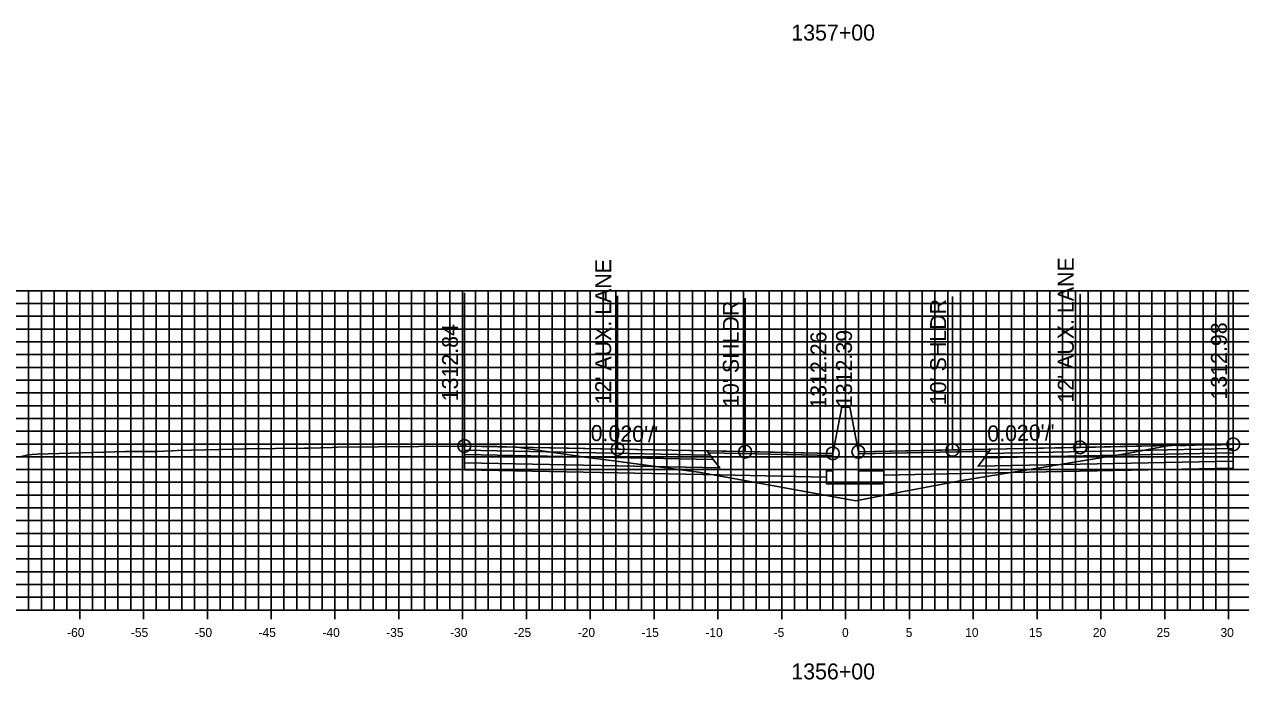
# Model space of a CAD drawing. Extents: x 674939 to 678919, y 750652 to 765176.
# Drawn here: x 678674.2 to 678769.5, y 753742.1 to 753793.4 of the extents above; entities that cross this region are included whole.
import ezdxf

# ---------------------------------------------------------------- set-up
doc = ezdxf.new("R2010")
doc.units = 0
for name, color, linetype in [('Level 10', 7, 'Continuous'), ('Level 17', 7, 'Continuous'), ('Level 18', 7, 'Continuous'), ('Level 19', 7, 'Continuous'), ('Level 20', 7, 'Continuous'), ('Level 22', 7, 'Continuous'), ('Level 23', 7, 'Continuous'), ('Level 4', 7, 'Continuous'), ('Level 8', 7, 'Continuous'), ('Level 9', 7, 'Continuous')]:
    doc.layers.add(name, color=color, linetype=linetype)

msp = doc.modelspace()

# ---------------------------------------------------------------- linework, layer by layer
at = {"layer": 'Level 10'}
msp.add_lwpolyline([(678673.696, 753759.531), (678674.327, 753759.663), (678674.356, 753759.666), (678674.804, 753759.734), (678675.19, 753759.744), (678682.129, 753759.956), (678682.267, 753759.958), (678684.516, 753759.968), (678684.604, 753759.969), (678684.634, 753759.971), (678685.137, 753759.996), (678685.157, 753759.997), (678685.779, 753760.029), (678686.181, 753760.038), (678691.617, 753760.166), (678696.114, 753760.216), (678696.405, 753760.219), (678696.417, 753760.218), (678696.455, 753760.223), (678698.329, 753760.287), (678698.696, 753760.292), (678708.309, 753760.389), (678708.576, 753760.391), (678708.668, 753760.393), (678708.677, 753760.393), (678708.805, 753760.394), (678708.869, 753760.39), (678710.367, 753760.35), (678710.468, 753760.351), (678711.218, 753760.352), (678712.717, 753760.298), (678712.806, 753760.296), (678714.737, 753760.016), (678717.61, 753759.598), (678718.097, 753759.528), (678720.168, 753759.252), (678727.002, 753758.341), (678730.892, 753757.635), (678739.341, 753756.11), (678742.378, 753756.695), (678747.651, 753757.691), (678752.616, 753758.5), (678760.729, 753759.828), (678763.193, 753760.303), (678764.325, 753760.508), (678764.396, 753760.507), (678764.486, 753760.487), (678764.766, 753760.427), (678764.886, 753760.425), (678765.185, 753760.445), (678766.586, 753760.473), (678767.244, 753760.473), (678767.945, 753760.473), (678768.698, 753760.51), (678768.877, 753760.53), (678768.906, 753760.529), (678769.135, 753760.54), (678769.823, 753760.534)], dxfattribs=at)
at = {"layer": 'Level 17'}
for points in [[(678738.203, 753763.315), (678737.533, 753759.815)], [(678738.863, 753763.442), (678738.863, 753763.442), (678738.203, 753763.442), (678738.203, 753763.315)], [(678738.863, 753763.442), (678739.533, 753759.942)], [(678737.533, 753759.815), (678737.533, 753758.44), (678737.033, 753758.44), (678737.033, 753757.44), (678741.533, 753757.44), (678741.533, 753758.44), (678739.533, 753758.44), (678739.533, 753759.942)]]:
    msp.add_lwpolyline(points, dxfattribs=at)
at = {"layer": 'Level 18'}
for points in [[(678737.533, 753759.815), (678730.668, 753759.953), (678720.668, 753760.153), (678708.668, 753760.393)], [(678768.906, 753760.529), (678756.906, 753760.289), (678746.906, 753760.089), (678739.533, 753759.942)]]:
    msp.add_lwpolyline(points, dxfattribs=at)
for points in [[(678708.668, 753760.393), (678708.668, 753760.063), (678727.918, 753759.678), (678727.668, 753760.013)], [(678727.668, 753760.013), (678737.533, 753759.815), (678737.537, 753759.658), (678727.787, 753759.853)], [(678749.787, 753759.99), (678739.533, 753759.785), (678739.533, 753759.942), (678749.906, 753760.149)], [(678768.906, 753760.529), (678768.906, 753760.199), (678749.656, 753759.814), (678749.906, 753760.149)]]:
    msp.add_lwpolyline(points, close=True, dxfattribs=at)
at = {"layer": 'Level 19'}
for points in [[(678708.668, 753760.063), (678708.668, 753759.733), (678728.168, 753759.343), (678727.918, 753759.678)], [(678768.906, 753760.199), (678768.906, 753759.869), (678749.406, 753759.479), (678749.656, 753759.814)], [(678708.668, 753759.733), (678708.668, 753759.073), (678728.668, 753758.673), (678728.168, 753759.343)], [(678768.906, 753759.869), (678768.906, 753759.209), (678748.906, 753758.809), (678749.406, 753759.479)]]:
    msp.add_lwpolyline(points, close=True, dxfattribs=at)
for points in [[(678708.668, 753759.073), (678708.668, 753758.533), (678728.668, 753758.133), (678737.033, 753757.965)], [(678768.906, 753759.209), (678768.906, 753758.669), (678748.906, 753758.269), (678741.533, 753758.122)]]:
    msp.add_lwpolyline(points, dxfattribs=at)
at = {"layer": 'Level 20'}
for p, q in [((678638.533, 753772.551), (678838.533, 753772.551)), ((678674.533, 753747.551), (678674.533, 753772.551)), ((678675.533, 753747.551), (678675.533, 753772.551)), ((678676.533, 753747.551), (678676.533, 753772.551)), ((678677.533, 753747.551), (678677.533, 753772.551)), ((678678.533, 753747.551), (678678.533, 753772.551)), ((678679.533, 753747.551), (678679.533, 753772.551)), ((678680.533, 753747.551), (678680.533, 753772.551)), ((678681.533, 753747.551), (678681.533, 753772.551)), ((678682.533, 753747.551), (678682.533, 753772.551)), ((678683.533, 753747.551), (678683.533, 753772.551)), ((678684.533, 753747.551), (678684.533, 753772.551)), ((678685.533, 753747.551), (678685.533, 753772.551)), ((678686.533, 753747.551), (678686.533, 753772.551)), ((678687.533, 753747.551), (678687.533, 753772.551)), ((678688.533, 753747.551), (678688.533, 753772.551)), ((678689.533, 753747.551), (678689.533, 753772.551)), ((678690.533, 753747.551), (678690.533, 753772.551)), ((678691.533, 753747.551), (678691.533, 753772.551)), ((678692.533, 753747.551), (678692.533, 753772.551)), ((678693.533, 753747.551), (678693.533, 753772.551)), ((678694.533, 753747.551), (678694.533, 753772.551)), ((678695.533, 753747.551), (678695.533, 753772.551)), ((678696.533, 753747.551), (678696.533, 753772.551)), ((678697.533, 753747.551), (678697.533, 753772.551)), ((678698.533, 753747.551), (678698.533, 753772.551)), ((678699.533, 753747.551), (678699.533, 753772.551)), ((678700.533, 753747.551), (678700.533, 753772.551)), ((678701.533, 753747.551), (678701.533, 753772.551)), ((678702.533, 753747.551), (678702.533, 753772.551)), ((678703.533, 753747.551), (678703.533, 753772.551)), ((678704.533, 753747.551), (678704.533, 753772.551)), ((678705.533, 753747.551), (678705.533, 753772.551)), ((678706.533, 753747.551), (678706.533, 753772.551)), ((678707.533, 753747.551), (678707.533, 753772.551)), ((678708.533, 753747.551), (678708.533, 753772.551)), ((678709.533, 753747.551), (678709.533, 753772.551)), ((678710.533, 753747.551), (678710.533, 753772.551)), ((678711.533, 753747.551), (678711.533, 753772.551)), ((678712.533, 753747.551), (678712.533, 753772.551)), ((678713.533, 753747.551), (678713.533, 753772.551)), ((678714.533, 753747.551), (678714.533, 753772.551)), ((678715.533, 753747.551), (678715.533, 753772.551)), ((678716.533, 753747.551), (678716.533, 753772.551)), ((678717.533, 753747.551), (678717.533, 753772.551)), ((678718.533, 753747.551), (678718.533, 753772.551)), ((678719.533, 753747.551), (678719.533, 753772.551)), ((678720.533, 753747.551), (678720.533, 753772.551)), ((678721.533, 753747.551), (678721.533, 753772.551)), ((678722.533, 753747.551), (678722.533, 753772.551)), ((678723.533, 753747.551), (678723.533, 753772.551)), ((678724.533, 753747.551), (678724.533, 753772.551)), ((678725.533, 753747.551), (678725.533, 753772.551)), ((678726.533, 753747.551), (678726.533, 753772.551)), ((678727.533, 753747.551), (678727.533, 753772.551)), ((678728.533, 753747.551), (678728.533, 753772.551)), ((678729.533, 753747.551), (678729.533, 753772.551)), ((678730.533, 753747.551), (678730.533, 753772.551)), ((678731.533, 753747.551), (678731.533, 753772.551)), ((678732.533, 753747.551), (678732.533, 753772.551)), ((678733.533, 753747.551), (678733.533, 753772.551)), ((678734.533, 753747.551), (678734.533, 753772.551)), ((678735.533, 753747.551), (678735.533, 753772.551)), ((678736.533, 753747.551), (678736.533, 753772.551)), ((678737.533, 753747.551), (678737.533, 753772.551)), ((678738.533, 753747.551), (678738.533, 753772.551)), ((678739.533, 753747.551), (678739.533, 753772.551)), ((678740.533, 753747.551), (678740.533, 753772.551)), ((678741.533, 753747.551), (678741.533, 753772.551)), ((678742.533, 753747.551), (678742.533, 753772.551)), ((678743.533, 753747.551), (678743.533, 753772.551)), ((678744.533, 753747.551), (678744.533, 753772.551)), ((678745.533, 753747.551), (678745.533, 753772.551)), ((678746.533, 753747.551), (678746.533, 753772.551)), ((678747.533, 753747.551), (678747.533, 753772.551)), ((678748.533, 753747.551), (678748.533, 753772.551)), ((678749.533, 753747.551), (678749.533, 753772.551)), ((678750.533, 753747.551), (678750.533, 753772.551)), ((678751.533, 753747.551), (678751.533, 753772.551)), ((678752.533, 753747.551), (678752.533, 753772.551)), ((678753.533, 753747.551), (678753.533, 753772.551)), ((678754.533, 753747.551), (678754.533, 753772.551)), ((678755.533, 753747.551), (678755.533, 753772.551)), ((678756.533, 753747.551), (678756.533, 753772.551)), ((678757.533, 753747.551), (678757.533, 753772.551)), ((678758.533, 753747.551), (678758.533, 753772.551)), ((678759.533, 753747.551), (678759.533, 753772.551)), ((678760.533, 753747.551), (678760.533, 753772.551)), ((678761.533, 753747.551), (678761.533, 753772.551)), ((678762.533, 753747.551), (678762.533, 753772.551)), ((678763.533, 753747.551), (678763.533, 753772.551)), ((678764.533, 753747.551), (678764.533, 753772.551)), ((678765.533, 753747.551), (678765.533, 753772.551)), ((678766.533, 753747.551), (678766.533, 753772.551)), ((678767.533, 753747.551), (678767.533, 753772.551)), ((678768.533, 753747.551), (678768.533, 753772.551)), ((678638.533, 753771.551), (678838.533, 753771.551)), ((678638.533, 753770.551), (678838.533, 753770.551)), ((678638.533, 753769.551), (678838.533, 753769.551)), ((678638.533, 753768.551), (678838.533, 753768.551)), ((678638.533, 753767.551), (678838.533, 753767.551)), ((678638.533, 753766.551), (678838.533, 753766.551)), ((678638.533, 753765.551), (678838.533, 753765.551)), ((678638.533, 753764.551), (678838.533, 753764.551)), ((678638.533, 753763.551), (678838.533, 753763.551)), ((678638.533, 753762.551), (678838.533, 753762.551)), ((678638.533, 753761.551), (678838.533, 753761.551)), ((678638.533, 753760.551), (678838.533, 753760.551)), ((678638.533, 753759.551), (678838.533, 753759.551)), ((678638.533, 753758.551), (678838.533, 753758.551)), ((678638.533, 753757.551), (678838.533, 753757.551)), ((678638.533, 753756.551), (678838.533, 753756.551)), ((678638.533, 753755.551), (678838.533, 753755.551)), ((678638.533, 753754.551), (678838.533, 753754.551)), ((678638.533, 753753.551), (678838.533, 753753.551)), ((678638.533, 753752.551), (678838.533, 753752.551)), ((678638.533, 753751.551), (678838.533, 753751.551)), ((678638.533, 753750.551), (678838.533, 753750.551)), ((678638.533, 753749.551), (678838.533, 753749.551)), ((678638.533, 753748.551), (678838.533, 753748.551)), ((678638.533, 753747.551), (678838.533, 753747.551))]:
    msp.add_line(p, q, dxfattribs=at)
at = {"layer": 'Level 23'}
for p, q in [((678708.668, 753760.393), (678708.668, 753772.393)), ((678768.906, 753760.529), (678768.906, 753772.529)), ((678720.668, 753760.153), (678720.668, 753772.153)), ((678730.668, 753759.953), (678730.668, 753771.953)), ((678737.533, 753759.815), (678737.533, 753771.815)), ((678739.533, 753759.942), (678739.533, 753771.942)), ((678746.906, 753760.089), (678746.906, 753772.089)), ((678756.906, 753760.289), (678756.906, 753772.289))]:
    msp.add_line(p, q, dxfattribs=at)
at = {"layer": 'Level 4'}
for centre in [(678708.668, 753760.393), (678768.906, 753760.529), (678720.668, 753760.153), (678730.668, 753759.953), (678737.533, 753759.815), (678739.533, 753759.942), (678746.906, 753760.089), (678756.906, 753760.289)]:
    msp.add_circle(centre, 0.5, dxfattribs=at)
at = {"layer": 'Level 8'}
for p, q in [((678638.533, 753747.551), (678838.533, 753747.551)), ((678678.533, 753746.851), (678678.533, 753748.251)), ((678683.533, 753746.851), (678683.533, 753748.251)), ((678688.533, 753746.851), (678688.533, 753748.251)), ((678693.533, 753746.851), (678693.533, 753748.251)), ((678698.533, 753746.851), (678698.533, 753748.251)), ((678703.533, 753746.851), (678703.533, 753748.251)), ((678708.533, 753746.851), (678708.533, 753748.251)), ((678713.533, 753746.851), (678713.533, 753748.251)), ((678718.533, 753746.851), (678718.533, 753748.251)), ((678723.533, 753746.851), (678723.533, 753748.251)), ((678728.533, 753746.851), (678728.533, 753748.251)), ((678733.533, 753746.851), (678733.533, 753748.251)), ((678738.533, 753746.851), (678738.533, 753748.251)), ((678743.533, 753746.851), (678743.533, 753748.251)), ((678748.533, 753746.851), (678748.533, 753748.251)), ((678753.533, 753746.851), (678753.533, 753748.251)), ((678758.533, 753746.851), (678758.533, 753748.251)), ((678763.533, 753746.851), (678763.533, 753748.251)), ((678768.533, 753746.851), (678768.533, 753748.251))]:
    msp.add_line(p, q, dxfattribs=at)

# ---------------------------------------------------------------- texts
at = {"layer": 'Level 22'}
for rotation, p in [(358.85424, (678718.551, 753760.795)), (1.14576, (678749.646, 753760.744))]:
    msp.add_text("0.020'/'", height=1.25, rotation=rotation, dxfattribs=at).set_placement(p)
at = {"layer": 'Level 23'}
for s, p in [("12' AUX. LANE", (678720.168, 753763.653)), ("12' AUX. LANE", (678756.406, 753763.789)), ("10' SHLDR", (678730.168, 753763.453)), ("10' SHLDR", (678746.406, 753763.589)), ('1312.84', (678708.168, 753763.893)), ('1312.98', (678768.406, 753764.029)), ('1312.26', (678737.033, 753763.315)), ('1312.39', (678739.033, 753763.442))]:
    msp.add_text(s, height=1.25, rotation=90, dxfattribs=at).set_placement(p)
at = {"layer": 'Level 9'}
for s, height, p in [('1357+00', 1.25, (678734.281, 753792.126)), ('-60', 0.7, (678677.552, 753745.451)), ('-55', 0.7, (678682.546, 753745.451)), ('-50', 0.7, (678687.552, 753745.451)), ('-45', 0.7, (678692.546, 753745.451)), ('-40', 0.7, (678697.552, 753745.451)), ('-35', 0.7, (678702.546, 753745.451)), ('-30', 0.7, (678707.552, 753745.451)), ('-25', 0.7, (678712.546, 753745.451)), ('-20', 0.7, (678717.552, 753745.451)), ('-15', 0.7, (678722.546, 753745.451)), ('-10', 0.7, (678727.552, 753745.451)), ('-5', 0.7, (678732.896, 753745.451)), ('0', 0.7, (678738.252, 753745.451)), ('5', 0.7, (678743.246, 753745.451)), ('10', 0.7, (678747.902, 753745.451)), ('15', 0.7, (678752.896, 753745.451)), ('20', 0.7, (678757.902, 753745.451)), ('25', 0.7, (678762.896, 753745.451)), ('30', 0.7, (678767.902, 753745.451)), ('1356+00', 1.25, (678734.282, 753742.126))]:
    msp.add_text(s, height=height, dxfattribs=at).set_placement(p)

doc.saveas('drawing.dxf')
